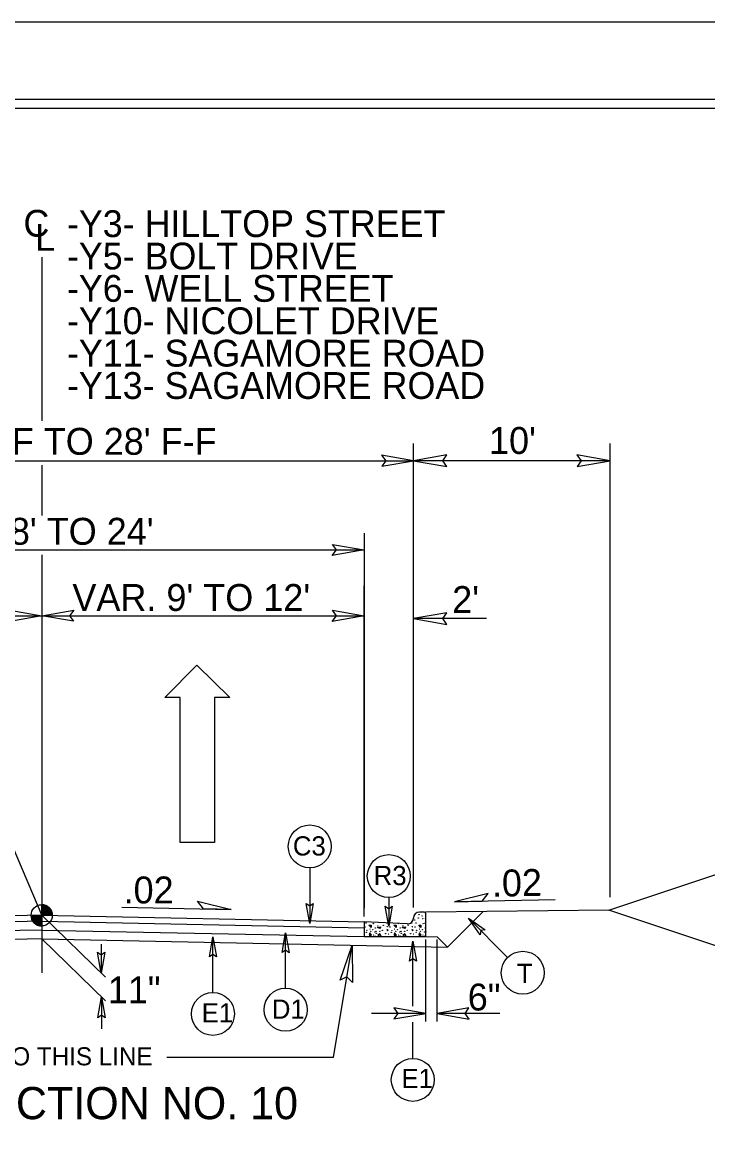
# Model space of a CAD drawing. Extents: x 958711 to 962106, y 831169 to 840840.
# Drawn here: x 959524.4 to 959723.1, y 835621.3 to 835942.4 of the extents above; entities that cross this region are included whole.
import ezdxf

# ---------------------------------------------------------------- set-up
doc = ezdxf.new("R2010")
doc.units = 0
for name, color, linetype in [('Default', 7, 'Continuous'), ('Old_Level_1', 7, 'Continuous'), ('Old_Level_11', 7, 'Continuous'), ('Old_Level_3', 7, 'Continuous'), ('Prop Dimension Text', 7, 'Continuous'), ('Prop Lane Arrow CELL', 7, 'Continuous'), ('Sheet Plot Border Inside CELL', 7, 'Continuous'), ('Sheet Plot Border Outside CELL', 7, 'Continuous'), ('Sheet Typical CELL', 7, 'Continuous'), ('Typical ID Circle CELL', 7, 'Continuous'), ('Typical Terminator CELL', 7, 'Continuous'), ('Typical Text Grade Point CELL', 7, 'Continuous'), ('Typical Text ID Circle CELL', 7, 'Continuous')]:
    doc.layers.add(name, color=color, linetype=linetype)

# ---------------------------------------------------------------- blocks, each defined once
blk = doc.blocks.new('Lane Arrow Through')
at = {"layer": 'Prop Lane Arrow CELL'}
for p, q in [((-3.15, 1.6), (-3.15, 3.1)), ((-3.15, 3.1), (0, 0)), ((-17.15, 1.6), (-3.15, 1.6)), ((-17.15, -1.7), (-17.15, 1.6)), ((0, 0), (-3.15, -3.2)), ((-3.15, -1.7), (-17.15, -1.7)), ((-3.15, -3.2), (-3.15, -1.7))]:
    blk.add_line(p, q, dxfattribs=at)

msp = doc.modelspace()

# ---------------------------------------------------------------- linework, layer by layer
at = {"layer": 'Default'}
for p, q in [((959530.11, 835874.3), (959530.11, 835826.88)), ((959530.11, 835814.02), (959530.11, 835799.41)), ((959530.11, 835787.96), (959530.11, 835666.84))]:
    msp.add_line(p, q, dxfattribs=at)
at = {"layer": 'Old_Level_1'}
for p, q in [((959637.88, 835685.74), (959637.88, 835820.25)), ((959694.85, 835688.76), (959694.85, 835820.25)), ((959422.39, 835815.3), (959637.88, 835815.3)), ((959694.85, 835815.3), (959637.88, 835815.3)), ((959623.59, 835794.28), (959623.59, 835685.6)), ((959436.63, 835789.43), (959623.59, 835789.43)), ((959623.59, 835683.16), (959623.59, 835779.06)), ((959436.63, 835770.36), (959530.11, 835770.36)), ((959530.11, 835770.36), (959623.59, 835770.36)), ((959658.99, 835769.58), (959637.88, 835769.58)), ((959694.48, 835685), (959771.66, 835710.73)), ((959530.11, 835683.5), (959530.11, 835686.57)), ((959553.33, 835685.85), (959585.04, 835685.21)), ((959678.92, 835688.05), (959649.7, 835687.46)), ((959530.11, 835683.51), (959436.63, 835681.62)), ((959527.05, 835683.5), (959530.11, 835683.5)), ((959530.11, 835683.51), (959623.59, 835681.62)), ((959530.11, 835683.51), (959548.58, 835665.58)), ((959533.17, 835683.5), (959530.11, 835683.5)), ((959530.11, 835680.45), (959530.11, 835683.5)), ((959530.11, 835683.5), (959530.11, 835680.45)), ((959694.48, 835685), (959641.39, 835684.47)), ((959647.66, 835674.31), (959657.99, 835684.63)), ((959771.66, 835659.27), (959694.48, 835685)), ((959530.11, 835681.78), (959436.63, 835679.89)), ((959530.11, 835679.23), (959436.63, 835677.34)), ((959530.11, 835681.78), (959623.59, 835679.89)), ((959530.11, 835679.23), (959623.59, 835677.34)), ((959530.11, 835676.68), (959412.55, 835674.31)), ((959530.11, 835676.68), (959548.58, 835658.75)), ((959530.11, 835676.68), (959647.66, 835674.31)), ((959641.39, 835677.34), (959644.69, 835677.28)), ((959641.39, 835652.78), (959641.39, 835676.54)), ((959644.69, 835677.28), (959647.66, 835674.31)), ((959644.69, 835652.78), (959644.69, 835676.54)), ((959547.37, 835675.12), (959547.37, 835666.75)), ((959614.71, 835642.3), (959620.08, 835674.86)), ((959547.43, 835659.86), (959547.43, 835650.64)), ((959641.39, 835655.08), (959625.63, 835655.08)), ((959662.84, 835655.08), (959644.69, 835655.08)), ((959614.71, 835642.3), (959566.39, 835642.3))]:
    msp.add_line(p, q, dxfattribs=at)
for points in [[(959530.14, 835686.57), (959530.14, 835686.57), (959530.14, 835683.5)], [(959530.2, 835686.57), (959530.2, 835683.5)], [(959530.26, 835686.56), (959530.26, 835683.5)], [(959530.33, 835686.55), (959530.33, 835683.5)], [(959530.39, 835686.55), (959530.39, 835683.5)], [(959530.45, 835686.55), (959530.45, 835683.5)], [(959530.51, 835686.53), (959530.51, 835683.5)], [(959530.57, 835686.53), (959530.57, 835683.5)], [(959530.62, 835686.51), (959530.62, 835683.5)], [(959530.68, 835686.51), (959530.68, 835683.5)], [(959530.75, 835686.5), (959530.75, 835683.5)], [(959530.81, 835686.48), (959530.81, 835683.5)], [(959530.87, 835686.46), (959530.87, 835683.5)], [(959530.93, 835686.44), (959530.93, 835683.5)], [(959531, 835686.43), (959531, 835683.5)], [(959531.06, 835686.41), (959531.06, 835683.5)], [(959531.12, 835686.39), (959531.12, 835683.5)], [(959531.18, 835686.37), (959531.18, 835683.5)], [(959531.24, 835686.35), (959531.24, 835683.5)], [(959531.31, 835686.32), (959531.31, 835683.5)], [(959531.37, 835686.3), (959531.37, 835683.5)], [(959531.43, 835686.26), (959531.43, 835683.5)], [(959531.48, 835686.24), (959531.48, 835683.5)], [(959531.54, 835686.22), (959531.54, 835683.5)], [(959531.6, 835686.18), (959531.6, 835683.5)], [(959531.67, 835686.14), (959531.67, 835683.5)], [(959531.73, 835686.1), (959531.73, 835683.5)], [(959531.79, 835686.06), (959531.79, 835683.5)], [(959531.85, 835686.01), (959531.85, 835683.5)], [(959531.91, 835685.98), (959531.91, 835683.5)], [(959531.98, 835685.93), (959531.98, 835683.5)], [(959532.04, 835685.88), (959532.04, 835683.5)], [(959532.1, 835685.84), (959532.1, 835683.5)], [(959532.16, 835685.78), (959532.16, 835683.5)], [(959532.22, 835685.71), (959532.22, 835683.5)], [(959532.29, 835685.65), (959532.29, 835683.5)], [(959532.34, 835685.59), (959532.34, 835683.5)], [(959532.4, 835685.53), (959532.4, 835683.5)], [(959532.46, 835685.46), (959532.46, 835683.5)], [(959532.52, 835685.37), (959532.52, 835683.5)], [(959527.07, 835683.5), (959527.07, 835683.18)], [(959527.13, 835683.5), (959527.13, 835682.81)], [(959527.19, 835683.5), (959527.19, 835682.59)], [(959527.25, 835683.5), (959527.25, 835682.41)], [(959527.32, 835683.5), (959527.32, 835682.27)], [(959527.38, 835683.5), (959527.38, 835682.14)], [(959527.43, 835683.5), (959527.43, 835682.02)], [(959527.49, 835683.5), (959527.49, 835681.91)], [(959527.56, 835683.5), (959527.56, 835681.83)], [(959527.62, 835683.5), (959527.62, 835681.73)], [(959527.68, 835683.5), (959527.68, 835681.64)], [(959527.74, 835683.5), (959527.74, 835681.58)], [(959527.81, 835683.5), (959527.81, 835681.51)], [(959527.86, 835683.5), (959527.86, 835681.43)], [(959527.92, 835683.5), (959527.92, 835681.36)], [(959527.99, 835683.5), (959527.99, 835681.31)], [(959528.05, 835683.5), (959528.05, 835681.26)], [(959528.11, 835683.5), (959528.11, 835681.2)], [(959528.17, 835683.5), (959528.17, 835681.15)], [(959528.24, 835683.5), (959528.24, 835681.09)], [(959528.29, 835683.5), (959528.29, 835681.05)], [(959528.35, 835683.5), (959528.35, 835681.01)], [(959528.41, 835683.5), (959528.41, 835680.97)], [(959528.47, 835683.5), (959528.47, 835680.91)], [(959528.54, 835683.5), (959528.54, 835680.88)], [(959528.6, 835683.5), (959528.6, 835680.84)], [(959528.66, 835683.5), (959528.66, 835680.81)], [(959528.72, 835683.5), (959528.72, 835680.79)], [(959528.78, 835683.5), (959528.78, 835680.75)], [(959528.85, 835683.5), (959528.85, 835680.72)], [(959528.91, 835683.5), (959528.91, 835680.7)], [(959528.97, 835683.5), (959528.97, 835680.66)], [(959529.03, 835683.5), (959529.03, 835680.65)], [(959529.09, 835683.5), (959529.09, 835680.63)], [(959529.14, 835683.5), (959529.14, 835680.6)], [(959529.21, 835683.5), (959529.21, 835680.59)], [(959529.27, 835683.5), (959529.27, 835680.57)], [(959529.33, 835683.5), (959529.33, 835680.55)], [(959529.39, 835683.5), (959529.39, 835680.54)], [(959529.45, 835683.5), (959529.45, 835680.52)], [(959529.52, 835683.5), (959529.52, 835680.5)], [(959529.58, 835683.5), (959529.58, 835680.5)], [(959529.64, 835683.5), (959529.64, 835680.49)], [(959529.7, 835683.5), (959529.7, 835680.47)], [(959529.77, 835683.5), (959529.77, 835680.47)], [(959529.83, 835683.5), (959529.83, 835680.47)], [(959529.89, 835683.5), (959529.89, 835680.45)], [(959529.95, 835683.5), (959529.95, 835680.45)], [(959530, 835683.5), (959530, 835680.45)], [(959530.06, 835683.5), (959530.06, 835680.45), (959530.06, 835680.45)], [(959532.59, 835685.3), (959532.59, 835683.5)], [(959532.65, 835685.21), (959532.65, 835683.5)], [(959532.71, 835685.12), (959532.71, 835683.5)], [(959532.77, 835685.02), (959532.77, 835683.5)], [(959532.83, 835684.91), (959532.83, 835683.5)], [(959532.89, 835684.77), (959532.89, 835683.5)], [(959532.95, 835684.62), (959532.95, 835683.5)], [(959533.02, 835684.46), (959533.02, 835683.5)], [(959533.08, 835684.25), (959533.08, 835683.5)], [(959533.14, 835683.94), (959533.14, 835683.5)]]:
    msp.add_lwpolyline(points, dxfattribs=at)
msp.add_circle((959530.11, 835683.51), 3.06, dxfattribs=at)
for centre, radius, start, end in [((959530.11, 835683.51), 3.06, 359.9905, 89.9905), ((959530.11, 835683.51), 3.06, 179.9905, 269.9905), ((959641.08, 835680.88), 0.309, 0, 90)]:
    msp.add_arc(centre, radius, start, end, dxfattribs=at)
at = {"layer": 'Old_Level_11'}
for p, q in [((959659.44, 835689.88), (959649.7, 835687.46)), ((959657.71, 835687.62), (959659.44, 835689.88)), ((959577.03, 835685.37), (959575.3, 835687.63)), ((959575.3, 835687.63), (959585.04, 835685.21)), ((959585.04, 835685.21), (959577.03, 835685.37)), ((959649.7, 835687.46), (959657.71, 835687.62))]:
    msp.add_line(p, q, dxfattribs=at)
for points in [[(959685.24, 835813.64), (959694.85, 835815.3), (959685.19, 835817.01), (959686.41, 835815.3)], [(959647.49, 835816.95), (959637.88, 835815.3), (959647.55, 835813.58), (959646.32, 835815.3)], [(959647.49, 835771.23), (959637.88, 835769.58), (959647.55, 835767.86), (959646.32, 835769.58)], [(959616.56, 835664.73), (959620.08, 835674.86), (959620.21, 835664.07), (959618.57, 835665.71)]]:
    msp.add_lwpolyline(points, close=True, dxfattribs=at)
at = {"layer": 'Old_Level_3'}
for p, q in [((959637.8, 835682.11), (959637.64, 835682.15)), ((959637.68, 835682.27), (959637.8, 835682.11)), ((959641.08, 835684.47), (959639.6, 835684.47)), ((959641.39, 835680.9), (959641.39, 835684.16)), ((959635.98, 835681), (959623.59, 835681.62)), ((959623.59, 835681.62), (959623.59, 835677.34)), ((959624.94, 835680.62), (959625.56, 835680.65)), ((959625.56, 835680.03), (959624.94, 835680.62)), ((959625.56, 835680.65), (959625.56, 835680.03)), ((959627.37, 835679.97), (959628.27, 835680.22)), ((959628.16, 835679.7), (959627.37, 835679.97)), ((959628.27, 835680.22), (959628.16, 835679.7)), ((959632.16, 835680.62), (959632.79, 835680.65)), ((959632.79, 835680.03), (959632.16, 835680.62)), ((959632.79, 835680.65), (959632.79, 835680.03)), ((959634.6, 835679.97), (959635.49, 835680.22)), ((959635.39, 835679.7), (959634.6, 835679.97)), ((959635.49, 835680.22), (959635.39, 835679.7)), ((959635.98, 835681), (959635.98, 835681)), ((959639.39, 835680.62), (959640.02, 835680.65)), ((959640.02, 835680.03), (959639.39, 835680.62)), ((959640.02, 835680.65), (959640.02, 835680.03)), ((959641.39, 835677.34), (959641.39, 835680.9)), ((959623.59, 835677.34), (959641.39, 835677.34)), ((959625.17, 835678.45), (959624.97, 835677.79)), ((959624.97, 835677.79), (959625.66, 835677.75)), ((959625.66, 835677.75), (959625.17, 835678.45)), ((959628.1, 835678.12), (959627.5, 835677.69)), ((959627.5, 835677.69), (959628.46, 835677.46)), ((959628.46, 835677.46), (959628.1, 835678.12)), ((959632.39, 835678.45), (959632.2, 835677.79)), ((959632.2, 835677.79), (959632.88, 835677.75)), ((959632.88, 835677.75), (959632.39, 835678.45)), ((959635.33, 835678.12), (959634.73, 835677.69)), ((959634.73, 835677.69), (959635.69, 835677.46)), ((959635.69, 835677.46), (959635.33, 835678.12)), ((959639.61, 835678.45), (959639.43, 835677.79)), ((959639.43, 835677.79), (959640.11, 835677.75)), ((959640.11, 835677.75), (959639.61, 835678.45))]:
    msp.add_line(p, q, dxfattribs=at)
for centre in [(959638.2, 835682.18), (959638.23, 835683.56), (959639.25, 835682.71), (959639.42, 835683.7), (959640.35, 835683.3), (959640.51, 835682.51), (959641.33, 835682.61), (959623.81, 835680.13), (959624.11, 835681.32), (959624.34, 835679.14), (959625.2, 835679.5), (959625.46, 835678.91), (959626.02, 835679.4), (959626.19, 835681.12), (959626.77, 835679.83), (959626.97, 835678.88), (959627.53, 835680.46), (959628.1, 835678.88), (959628.79, 835679.17), (959629.09, 835680.62), (959630.24, 835680.19), (959630.28, 835679.34), (959630.38, 835679.04), (959631.04, 835680.13), (959631.57, 835679.14), (959632.42, 835679.5), (959632.69, 835678.91), (959633.25, 835679.4), (959634, 835679.83), (959634.2, 835678.88), (959634.76, 835680.46), (959635.32, 835678.88), (959636.02, 835679.17), (959636.31, 835680.62), (959637.37, 835681.28), (959637.47, 835680.19), (959637.5, 835679.34), (959637.6, 835679.04), (959638.26, 835680.13), (959638.56, 835681.32), (959638.79, 835679.14), (959639.65, 835679.5), (959639.92, 835678.91), (959640.48, 835679.4), (959640.64, 835681.12), (959641.23, 835679.83), (959624.17, 835678.55), (959626.19, 835677.76), (959626.65, 835678.68), (959626.74, 835677.49), (959627.07, 835678.32), (959629.81, 835678.22), (959630.54, 835678.05), (959631.4, 835678.55), (959633.42, 835677.76), (959633.88, 835678.68), (959633.97, 835677.49), (959634.3, 835678.32), (959637.04, 835678.22), (959637.77, 835678.05), (959638.63, 835678.55), (959640.64, 835677.76), (959641.11, 835678.68), (959641.2, 835677.49)]:
    msp.add_circle(centre, 0.0464, dxfattribs=at)
for centre, radius, start, end in [((959636.07, 835682.76), 1.76, 267.1376, 358.9266), ((959639.61, 835682.69), 1.78, 90, 178.9266), ((959641.08, 835684.16), 0.309, 0, 90), ((959641.2, 835684.39), 0.0464, 169.6531, 280.3469), ((959630.14, 835681.28), 0.0464, 164.1199, 10.1626), ((959633.42, 835681.12), 0.0464, 162.062, 12.2205), ((959641.43, 835678.88), 0.0464, 150.4173, 209.5827)]:
    msp.add_arc(centre, radius, start, end, dxfattribs=at)
at = {"layer": 'Sheet Plot Border Inside CELL'}
msp.add_lwpolyline([(960390.3, 835919.97), (958723.8, 835919.97), (958723.8, 834864.87), (960390.3, 834864.87)], close=True, dxfattribs=at)
at = {"layer": 'Sheet Plot Border Outside CELL'}
msp.add_lwpolyline([(960394.8, 835942.42), (958710.8, 835942.42), (958710.8, 834842.42), (960394.8, 834842.42)], close=True, dxfattribs=at)
at = {"layer": 'Sheet Typical CELL'}
msp.add_lwpolyline([(960377.8, 835917.42), (958877.8, 835917.42), (958877.8, 834867.42), (960377.8, 834867.42)], close=True, dxfattribs=at)
at = {"layer": 'Typical ID Circle CELL'}
for p, q in [((959607.79, 835697.26), (959607.79, 835681.17)), ((959630.7, 835688.66), (959630.7, 835680.36)), ((959665.12, 835671.27), (959653.74, 835682.65)), ((959579.72, 835661.17), (959579.72, 835677.26)), ((959600.79, 835662.39), (959600.79, 835678.47)), ((959637.65, 835657.22), (959637.65, 835675.99)), ((959637.65, 835642.05), (959637.65, 835652.54))]:
    msp.add_line(p, q, dxfattribs=at)
for centre in [(959607.79, 835703.48), (959630.7, 835694.89), (959669.52, 835666.87), (959579.72, 835654.94), (959600.79, 835656.16), (959637.65, 835635.82)]:
    msp.add_circle(centre, 6.23, dxfattribs=at)
at = {"layer": 'Typical Terminator CELL'}
for points in [[(959628.66, 835813.71), (959637.88, 835815.3), (959628.61, 835816.94), (959629.79, 835815.3)], [(959614.36, 835791.02), (959623.59, 835789.43), (959614.31, 835787.79), (959615.49, 835789.43)], [(959520.88, 835771.95), (959530.11, 835770.36), (959520.83, 835768.72), (959522.01, 835770.36)], [(959539.33, 835768.78), (959530.11, 835770.36), (959539.38, 835772), (959538.2, 835770.36)], [(959614.36, 835771.95), (959623.59, 835770.36), (959614.31, 835768.72), (959615.49, 835770.36)], [(959608.78, 835686.93), (959607.79, 835681.17), (959606.76, 835686.96), (959607.79, 835686.23)], [(959631.7, 835686.13), (959630.7, 835680.36), (959629.68, 835686.16), (959630.7, 835685.42)], [(959657.12, 835677.87), (959653.74, 835682.65), (959658.57, 835679.27), (959657.32, 835679.07)], [(959578.73, 835671.49), (959579.72, 835677.26), (959580.75, 835671.46), (959579.72, 835672.2)], [(959599.8, 835672.71), (959600.79, 835678.47), (959601.81, 835672.68), (959600.79, 835673.42)], [(959636.66, 835670.22), (959637.65, 835675.99), (959638.68, 835670.19), (959637.65, 835670.93)], [(959548.41, 835672.82), (959547.37, 835666.75), (959546.29, 835672.85), (959547.37, 835672.08)], [(959546.39, 835653.79), (959547.43, 835659.86), (959548.51, 835653.76), (959547.43, 835654.53)], [(959632.17, 835653.49), (959641.39, 835655.08), (959632.12, 835656.72), (959633.29, 835655.08)], [(959653.91, 835656.67), (959644.69, 835655.08), (959653.96, 835653.44), (959652.78, 835655.08)]]:
    msp.add_lwpolyline(points, close=True, dxfattribs=at)
at = {"layer": 'Typical Text Grade Point CELL'}
msp.add_line((959521.71, 835703.28), (959530.11, 835683.5), dxfattribs=at)

# ---------------------------------------------------------------- block references
at = {"layer": 'Old_Level_1', "xscale": 3, "yscale": 3, "rotation": 89.99999999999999}
msp.add_blockref('Lane Arrow Through', (959575.06, 835756.06), dxfattribs=at)

# ---------------------------------------------------------------- texts
at = {"layer": 'Old_Level_1'}
for s, height, p in [("VAR. 22' F-F TO 28' F-F", 7.8009, (959467.84, 835817.01)), ('GRADE TO THIS LINE', 5.2473, (959490.12, 835640.02)), ('TYPICAL SECTION NO. 10', 9.3239, (959450.57, 835624.42))]:
    msp.add_text(s, height=height, dxfattribs=at).set_placement(p)
at = {"layer": 'Old_Level_11'}
msp.add_text('11"', height=7.801, dxfattribs=at).set_placement((959549.25, 835657.99))
at = {"layer": 'Old_Level_3'}
for s, p in [("10'", (959659.73, 835817.25)), ("2'", (959649.05, 835771.14))]:
    msp.add_text(s, height=7.801, dxfattribs=at).set_placement(p)
at = {"layer": 'Prop Dimension Text'}
for s, height, rotation, p in [('C', 7.77, 0, (959524.81, 835880.22)), ('-Y3- HILLTOP STREET', 7.7675, 0, (959537.41, 835880.12)), ('L', 7.77, 0, (959528.2, 835876.13)), ('-Y5- BOLT DRIVE', 7.7675, 0, (959537.41, 835870.74)), ('-Y6- WELL STREET', 7.7675, 0, (959537.41, 835861.35)), ('-Y10- NICOLET DRIVE', 7.7675, 0, (959537.41, 835851.97)), ('-Y11- SAGAMORE ROAD', 7.7675, 0, (959537.41, 835842.58)), ('-Y13- SAGAMORE ROAD', 7.7675, 0, (959537.41, 835833.2)), ("VAR. 18' TO 24'", 7.8009, 0, (959487.82, 835790.93)), ("VAR. 9' TO 12'", 7.8009, 0, (959539, 835771.74)), ('.02', 7.801, 1.1839, (959660.65, 835688.88)), ('.02', 7.801, 360, (959553.84, 835686.96)), ('6"', 7.801, 0, (959653.57, 835655.92))]:
    msp.add_text(s, height=height, rotation=rotation, dxfattribs=at).set_placement(p)
at = {"layer": 'Typical Text ID Circle CELL'}
for s, height, p in [('C3', 5.572, (959602.9, 835700.85)), ('R3', 5.572, (959626.32, 835692.26)), ('T', 5.57, (959667.81, 835663.89)), ('E1', 5.572, (959576.46, 835652.46)), ('D1', 5.572, (959596.81, 835653.54)), ('E1', 5.572, (959634.35, 835633.44))]:
    msp.add_text(s, height=height, dxfattribs=at).set_placement(p)

doc.saveas('drawing.dxf')
